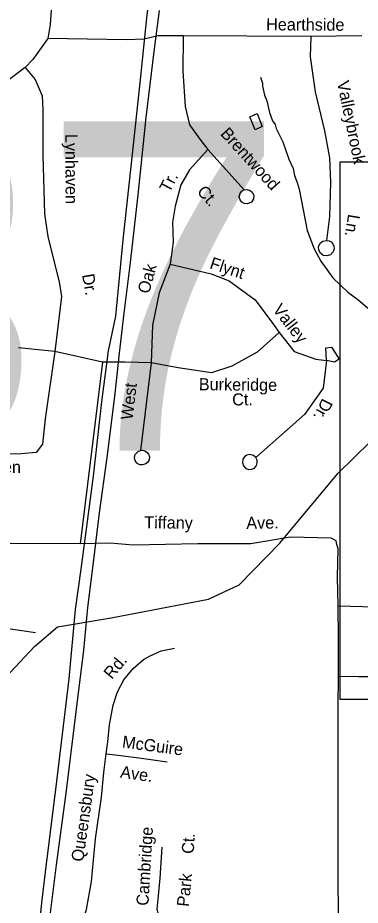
# Model space of a CAD drawing. Extents: x 1551653 to 1702041, y 811336 to 920032.
# Drawn here: x 1604617 to 1606474, y 851024 to 855842 of the extents above; entities that cross this region are included whole.
import ezdxf

# ---------------------------------------------------------------- set-up
doc = ezdxf.new("R2010")
doc.units = 0
for name, color, linetype in [('Old_Level_10', 7, 'Continuous'), ('Old_Level_3', 7, 'Continuous'), ('Old_Level_35', 7, 'Continuous'), ('Old_Level_56', 7, 'Continuous'), ('Old_Level_59', 7, 'Continuous'), ('Old_Level_62', 7, 'Continuous')]:
    doc.layers.add(name, color=color, linetype=linetype)

msp = doc.modelspace()

# ---------------------------------------------------------------- linework, layer by layer
at = {"layer": 'Old_Level_3'}
msp.add_lwpolyline([(1613201.763, 852140.276), (1606365.246, 852140.276), (1606365.246, 852523.519), (1606365.246, 855058.878), (1606567.302, 855058.878), (1613201.763, 855058.878), (1613201.763, 852140.276)], dxfattribs=at)
at = {"layer": 'Old_Level_35'}
for p, q in [((1606207.257, 855740.303), (1605515.075, 855742.77)), ((1606482.522, 855742.831), (1606207.257, 855740.303)), ((1605648.491, 855126.523), (1605845.518, 854907.054)), ((1604817.728, 854029.965), (1604621.82, 854050.436)), ((1605076.803, 853971.694), (1604817.728, 854029.965)), ((1605076.803, 853971.694), (1604954.829, 852985.661)), ((1605340.213, 853968.27), (1605282.686, 853493.067)), ((1604954.829, 852985.661), (1603969.604, 852989.084)), ((1604565.664, 852525.499), (1604712.763, 852504.957))]:
    msp.add_line(p, q, dxfattribs=at)
for points in [[(1604828.053, 856164.741), (1604807.527, 856044.915), (1604800.686, 855907.971), (1604793.844, 855805.264), (1604779.578, 855729.076)], [(1604779.578, 855729.076), (1604698.19, 855615.228), (1604657.139, 855570.721)], [(1605515.075, 855742.77), (1605378.239, 855742.77), (1605302.978, 855725.652), (1605207.193, 855722.229), (1604779.578, 855729.076)], [(1605515.075, 855742.77), (1605511.655, 855551.049), (1605525.338, 855359.327), (1605549.284, 855260.044), (1605610.861, 855174.453), (1605648.491, 855126.523)], [(1606207.257, 855740.303), (1606202.206, 855629.1), (1606229.985, 855439.55), (1606280.493, 855227.254), (1606308.272, 855080.668), (1606313.322, 854946.719), (1606308.272, 854763.656), (1606291.72, 854632.869)], [(1604657.139, 855570.721), (1604561.353, 855498.826), (1604325.31, 855368.729), (1603949.009, 855183.855), (1603747.175, 855077.724), (1603624.022, 855012.675)], [(1604657.139, 855570.721), (1604711.65, 855506.675), (1604749.28, 855417.661), (1604752.701, 855342.342), (1604752.701, 855095.844), (1604762.964, 854777.449), (1604780.068, 854654.2), (1604821.12, 854486.444), (1604841.645, 854407.701), (1604855.329, 854328.959), (1604834.803, 854164.627), (1604817.728, 854029.965)], [(1605648.491, 855126.523), (1605549.284, 855016.968), (1605501.392, 854934.801), (1605470.604, 854818.4), (1605456.92, 854732.81), (1605460.341, 854623.255), (1605443.236, 854503.429)], [(1605845.518, 854907.054), (1605860.577, 854909.551), (1605877.687, 854904.6), (1605890.062, 854893.143), (1605896.949, 854877.595), (1605896.174, 854859.2), (1605884.977, 854839.816), (1605863.789, 854831.04), (1605845.216, 854833.019), (1605832.753, 854840.076), (1605822.608, 854852.887), (1605818.136, 854869.19), (1605822.762, 854890.105), (1605834.803, 854901.67), (1605845.518, 854907.054)], [(1606291.72, 854632.869), (1606305.083, 854630.595), (1606315.968, 854624.772), (1606324.974, 854614.982), (1606330.916, 854602.055), (1606332.232, 854588.02), (1606327.484, 854570.907), (1606313.16, 854555.389), (1606293.419, 854548.988), (1606272.868, 854551.806), (1606258.488, 854563.102), (1606249.417, 854579.496), (1606248.19, 854597.931), (1606257.803, 854618.148), (1606272.445, 854629.657), (1606291.72, 854632.869)], [(1605443.236, 854503.429), (1605384.685, 854348.289), (1605347.055, 854173.686), (1605340.213, 853968.27)], [(1605443.236, 854503.429), (1605665.2, 854450.997), (1605764.407, 854413.338), (1605904.664, 854310.63), (1606003.871, 854177.109), (1606034.659, 854132.603)], [(1606034.659, 854132.603), (1605914.927, 854026.472), (1605778.091, 853951.153), (1605668.621, 853913.493), (1605487.313, 853940.882), (1605340.213, 853968.27)], [(1606034.659, 854132.603), (1606116.761, 854029.895), (1606233.072, 853988.812), (1606291.228, 853981.965)], [(1604817.728, 854029.965), (1604765.499, 853663.57), (1604751.815, 853526.627), (1604717.606, 853482.121), (1604635.504, 853475.273), (1604505.509, 853471.849), (1604385.777, 853465.002)], [(1606291.228, 853981.965), (1606287.807, 854050.436), (1606318.596, 854053.861), (1606339.121, 854023.048), (1606359.646, 853988.812), (1606335.7, 853971.694), (1606291.228, 853981.965)], [(1605340.213, 853968.27), (1605199.955, 853971.694), (1605076.803, 853971.694)], [(1606291.228, 853981.965), (1606274.123, 853831.327), (1606171.496, 853687.536), (1605908.085, 853454.731)], [(1605282.686, 853493.067), (1605294.109, 853493.838), (1605306.265, 853491.391), (1605319.894, 853482.509), (1605327.082, 853471.955), (1605331.413, 853458.461), (1605329.47, 853441.693), (1605321.367, 853426.847), (1605308.174, 853417.71), (1605294.09, 853413.992), (1605279.103, 853415.098), (1605263.289, 853424.622), (1605253.772, 853438.825), (1605250.901, 853455.091), (1605254.228, 853471.233), (1605269.375, 853487.936), (1605282.686, 853493.067)], [(1605915.517, 853426.365), (1605915.375, 853439.174), (1605908.085, 853454.731), (1605895.1, 853465.601), (1605876.58, 853469.977), (1605860.307, 853466.907), (1605847.521, 853457.96), (1605838.45, 853444.938), (1605836.091, 853427.176), (1605841.517, 853408.655), (1605854.654, 853395.381), (1605870.146, 853389.663), (1605887.187, 853391.119), (1605900.32, 853397.458), (1605911.596, 853410.634), (1605915.517, 853426.365)], [(1606355.042, 852648.889), (1606351.804, 852804.843), (1606354.724, 852958.669), (1606347.211, 852982.835), (1606343.615, 853002.92), (1606327.772, 853011.044), (1606315.892, 853017.291), (1606096.057, 853021.349), (1605881.897, 852985.661), (1605594.54, 852985.661), (1605242.185, 852978.814), (1605119.033, 852989.084), (1604954.829, 852985.661)], [(1606355.863, 852265.058), (1606355.718, 852474.979), (1606355.042, 852648.889)], [(1606355.042, 852648.889), (1606488.864, 852646.376), (1606704.54, 852644.401), (1606848.401, 852643.682), (1606908.053, 852634.667), (1606914.831, 852564.493), (1606921.833, 852406.462), (1606927.197, 852266.475)], [(1605097.499, 851846.341), (1605106.597, 851910.193), (1605114.307, 852004.087), (1605134.254, 852109.543), (1605157.558, 852183.112), (1605192.702, 852248.434), (1605243.765, 852309.434), (1605298.791, 852358.545), (1605335.002, 852377.823), (1605395.376, 852404.611), (1605467.715, 852419.355)], [(1606366.017, 850437.83), (1606360.449, 850567.817), (1606357.441, 850833.824), (1606355.367, 851155.647), (1606354.472, 851545.482), (1606354.78, 852103.191), (1606355.863, 852265.058)], [(1606927.197, 852266.475), (1606789.454, 852263.066), (1606615.583, 852264.192), (1606465.679, 852263.03), (1606355.863, 852265.058)], [(1604930.272, 850833.565), (1604958.185, 850907.439), (1604989.897, 851000.848), (1605016.584, 851152.393), (1605038.89, 851383.869), (1605071.114, 851611.145), (1605083.631, 851744.764), (1605097.499, 851846.341)], [(1605097.499, 851846.341), (1605161.19, 851839.245), (1605300.688, 851820.807), (1605428.184, 851802.411)], [(1605397.792, 851340.004), (1605387.815, 851170.817), (1605376.421, 851056.226), (1605371.06, 851002.301), (1605386.033, 850946.362), (1605436.237, 850900.548), (1605497.481, 850871.356), (1605554.017, 850852.167)]]:
    msp.add_lwpolyline(points, dxfattribs=at)
at = {"layer": 'Old_Level_56'}
for points in [[(1605615.864, 858321.253), (1605580.969, 858130.056), (1605552.327, 857842.675), (1605501.602, 857413.663), (1605455.976, 857058.588), (1605430.635, 856845.183), (1605398.197, 856567.887), (1605351.268, 856128.793), (1605316.951, 855857.537), (1605279.041, 855488.299), (1605229.992, 855033.438), (1605187.715, 854636.274), (1605147.079, 854221.264), (1605108.06, 854033.952), (1605071.82, 853756.731), (1605025.422, 853353.645), (1604986.695, 853052.461), (1604959.353, 852848.902), (1604927.89, 852629.617), (1604894.022, 852252.292), (1604822.408, 851651.811), (1604771.824, 851249.61), (1604747.034, 851053.403), (1604709.327, 850694.165)], [(1605383.25, 855880.405), (1605355.746, 855659.037), (1605312.039, 855299.924), (1605267.522, 854880.991), (1605227.656, 854513.793), (1605193.257, 854238.538), (1605167.83, 854020.93), (1605142.043, 853785.524), (1605100.904, 853454.373), (1605058.178, 853153.268), (1605025.898, 852883.974), (1604996.144, 852640.441), (1604974.441, 852408.952), (1604930.938, 852059.838), (1604878.057, 851633.071), (1604825.941, 851244.108), (1604793.825, 850982.813)]]:
    msp.add_lwpolyline(points, dxfattribs=at)
at = {"layer": 'Old_Level_59'}
msp.add_lwpolyline([(1603267.592, 850997.272), (1603446.176, 851092.59), (1603489.036, 851168.845), (1603543.801, 851395.228), (1603678.613, 851694.44), (1603816.613, 851990.381), (1603873.491, 852138.839), (1604007.493, 852218.194), (1604578.689, 852290.014), (1604707.308, 852429.446), (1604833.312, 852535.202), (1605124.64, 852584.264), (1605651.624, 852685.15), (1605818.639, 852763.838), (1606038.66, 852989.139), (1606352.697, 853366.896), (1606529.657, 853540.524)], dxfattribs=at)
at = {"layer": 'Old_Level_62'}
for points in [[(1605932.751, 855518.405), (1605944.234, 855486.264), (1605944.029, 855470.27), (1605955.409, 855422.133), (1605966.994, 855389.992), (1605982.066, 855327.758), (1605999.495, 855281.57), (1606013.131, 855261.372), (1606018.873, 855241.277), (1606053.834, 855168.791), (1606086.54, 855074.365), (1606109.916, 855024.076), (1606117.4, 854985.987), (1606132.779, 854947.745), (1606142.314, 854911.656), (1606187.22, 854687.073), (1606223.822, 854586.546), (1606260.937, 854520.058), (1606325.631, 854429.168), (1606406.524, 854352.069), (1606461.99, 854311.315), (1606604.194, 854191.36)], [(1605914.604, 855322.735), (1605943.106, 855251.787), (1605905.274, 855234.1), (1605875.131, 855303.716), (1605914.604, 855322.735)]]:
    msp.add_lwpolyline(points, dxfattribs=at)

# ---------------------------------------------------------------- texts
at = {"layer": 'Old_Level_10'}
for s, height, rotation, p in [('Hearthside', 65.6167, 359.677544, (1605964.03, 855773.358)), ('Valleybrook', 65.61666, 281.669703, (1606348.129, 855492.204)), ('Brentwood', 65.6167, 312.364253, (1605712.295, 855209.08)), ('Lynhaven', 65.6167, 270.170331, (1604875.593, 855211.041)), ('Tr.', 65.6167, 62.409033, (1605440.086, 854887.848)), ('Ct.', 65.6167, 312.364253, (1605585.224, 854894.838)), ('Ln.', 65.6167, 260.268236, (1606409.654, 854778.435)), ('Oak', 65.6167, 74.779714, (1605329.057, 854339.638)), ('Flynt', 65.6167, 341.621814, (1605653.632, 854482.319)), ('Dr.', 65.6167, 279.645878, (1604965.765, 854446.271)), ('Valley', 65.6167, 307.943886, (1605996.165, 854256.624)), ('Burkeridge', 65.6167, 359.441964, (1605599.031, 853819.758)), ('West', 65.6167, 83.198258, (1605239.867, 853656.028)), ('Ct.', 65.6167, 0.783336, (1605780.523, 853736.724)), ('Dr.', 65.6167, 242.964772, (1606269.857, 853779.831)), ('Lynhaven', 65.6167, 0.132678, (1604254.193, 853369.044)), ('Tiffany', 65.6167, 359.307156, (1605302.808, 853070.303)), ('Ave.', 65.6167, 0.984331, (1605857.022, 853066.428)), ('Rd.', 65.6167, 50.067661, (1605126.975, 852246.805)), ('McGuire', 65.6167, 352.470508, (1605180.661, 851880.297)), ('Ave.', 65.6167, 351.789825, (1605170.094, 851717.277)), ('Queensbury', 65.6167, 81.930119, (1604971.613, 851257.684)), ('Cambridge', 65.6167, 86.625153, (1605325.457, 851019.903)), ('Ct.', 65.6167, 86.625153, (1605571.223, 851301.486)), ('Park', 65.6167, 84.321892, (1605544.645, 851013.887))]:
    msp.add_text(s, height=height, rotation=rotation, dxfattribs=at).set_placement(p)
at = {"layer": 'Old_Level_3'}
msp.add_text('U-3837', height=1788.0542, dxfattribs=at).set_placement((1598230.486, 853490.887))

doc.saveas('drawing.dxf')
